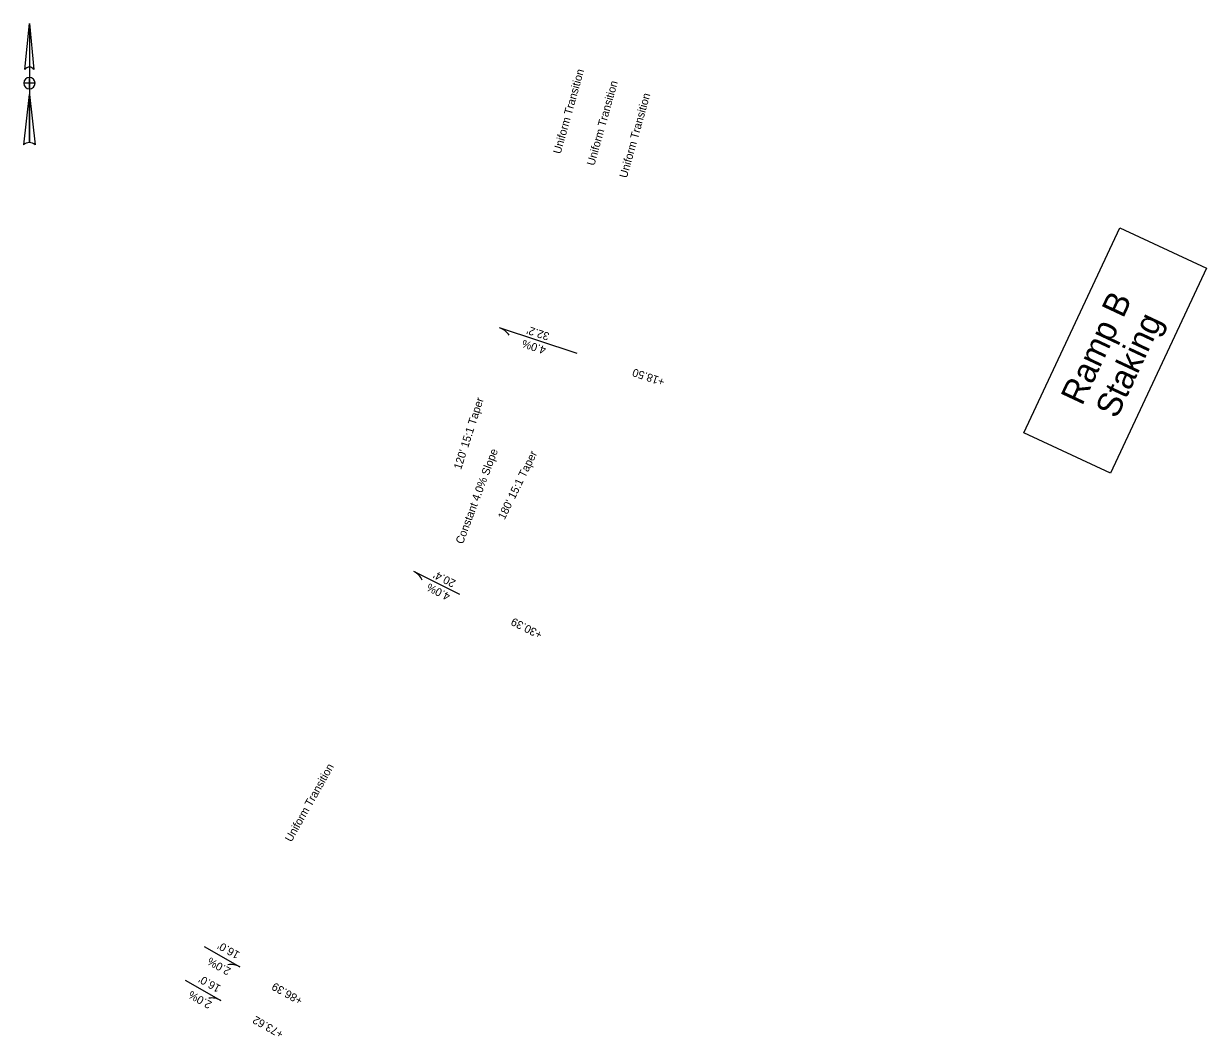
# Model space of a CAD drawing. Extents: x 20506035 to 20507470, y 7969245 to 7972296.
# Drawn here: x 20506911.7 to 20507305.4, y 7970023.2 to 7970360 of the extents above; entities that cross this region are included whole.
import ezdxf

# ---------------------------------------------------------------- set-up
doc = ezdxf.new("R2010")
doc.units = 0
for name, color, linetype in [('_CIVIL_CONSTRUCTION', 7, 'Continuous'), ('EdgeShoulder', 7, 'Continuous'), ('Joints', 7, 'Continuous')]:
    doc.layers.add(name, color=color, linetype=linetype)

msp = doc.modelspace()

# ---------------------------------------------------------------- linework, layer by layer
at = {"layer": '_CIVIL_CONSTRUCTION'}
for p, q in [((20507095.99, 7970250.25), (20507070.17, 7970258.82)), ((20507056.87, 7970170.12), (20507041.62, 7970177.83)), ((20506971.79, 7970053.01), (20506983.66, 7970046.28)), ((20506965.48, 7970041.87), (20506977.35, 7970035.15))]:
    msp.add_line(p, q, dxfattribs=at)
for centre, start, end in [((20507068.23, 7970252.97), 33.455, 71.658), ((20507038.84, 7970172.32), 25.0169, 63.2199), ((20506980.63, 7970040.92), 60.4958, 98.6465), ((20506974.32, 7970029.78), 60.4958, 98.6465)]:
    msp.add_arc(centre, 6.16, start, end, dxfattribs=at)
at = {"layer": 'EdgeShoulder'}
for p, q in [((20506913.65, 7970360.01), (20506915.17, 7970344.79)), ((20506913.65, 7970360.01), (20506913.65, 7970320.46)), ((20506912.18, 7970344.94), (20506912.47, 7970345.25)), ((20506912.13, 7970344.79), (20506912.13, 7970344.79)), ((20506913.65, 7970338.33), (20506913.65, 7970338.33)), ((20506911.75, 7970319.69), (20506913.65, 7970336.43))]:
    msp.add_line(p, q, dxfattribs=at)
for points in [[(20506912.13, 7970344.79), (20506913.65, 7970360.01), (20506913.65, 7970345.56)], [(20506915.55, 7970340.23), (20506913.65, 7970340.23), (20506913.65, 7970342.13)], [(20506913.65, 7970338.33), (20506913.65, 7970340.23), (20506911.75, 7970340.23)], [(20506913.65, 7970320.46), (20506913.65, 7970336.43), (20506915.55, 7970319.69)]]:
    msp.add_lwpolyline(points, dxfattribs=at)
for centre, radius, start, end in [((20506913.65, 7970343.65), 1.9, 90.0204, 143.1257), ((20506913.65, 7970343.66), 1.9, 36.8481, 90.0218), ((20506913.65, 7970340.23), 1.9, 90, 180), ((20506913.65, 7970340.23), 1.9, 0, 90), ((20506913.65, 7970340.23), 1.9, 180, 270), ((20506913.65, 7970340.23), 1.9, 270, 360), ((20506913.65, 7970317.7), 2.76, 89.9894, 133.619), ((20506913.65, 7970317.7), 2.76, 46.4021, 90.0006)]:
    msp.add_arc(centre, radius, start, end, dxfattribs=at)
at = {"layer": 'Joints'}
for points in [[(20507305.39, 7970278.66), (20507273.44, 7970210.46), (20507244.64, 7970223.95), (20507276.59, 7970292.15)], [(20507244.64, 7970223.95), (20507276.59, 7970292.15), (20507305.39, 7970278.66), (20507273.44, 7970210.46)]]:
    msp.add_lwpolyline(points, close=True, dxfattribs=at)

# ---------------------------------------------------------------- texts
at = {"layer": '_CIVIL_CONSTRUCTION'}
for s, rotation, p in [('Uniform Transition', 74.3157, (20507090.45, 7970316.49)), ('Uniform Transition', 74.3157, (20507101.67, 7970312.58)), ('Uniform Transition', 74.3157, (20507112.5, 7970308.48)), ("32.2'", 161.7345, (20507086.97, 7970257.07)), ('4.0%', 161.7345, (20507085.84, 7970252.47)), ('+18.50', 161.6317, (20507125.34, 7970241.91)), ("120' 15:1 Taper", 72.2267, (20507057.33, 7970211.49)), ('Constant 4.0% Slope', 69.4262, (20507057.91, 7970186.71)), ("180' 15:1 Taper", 63.8643, (20507071.82, 7970194.82)), ("20.4'", 153.2964, (20507055.78, 7970174.72)), ('4.0%', 153.2964, (20507053.99, 7970170.34)), ('+30.39', 153.1937, (20507084.65, 7970157.58)), ('Uniform Transition', 60.6487, (20507000.86, 7970087.6)), ("16.0'", 150.5724, (20506983.9, 7970051.05)), ('2.0%', 150.5724, (20506980.94, 7970045.62)), ("16.0'", 150.5724, (20506977.59, 7970039.91)), ('2.0%', 150.5724, (20506974.63, 7970034.49)), ('+86.39', 150.4697, (20507004.88, 7970035.8)), ('+73.62', 150.4697, (20506998.53, 7970024.68))]:
    msp.add_text(s, height=2.664, rotation=rotation, dxfattribs=at).set_placement(p)
at = {"layer": 'Joints'}
for s, p in [('Ramp B', (20507264.03, 7970232.65)), ('Staking', (20507275.53, 7970228.35))]:
    msp.add_text(s, height=8.16, rotation=64.9006, dxfattribs=at).set_placement(p)

doc.saveas('drawing.dxf')
